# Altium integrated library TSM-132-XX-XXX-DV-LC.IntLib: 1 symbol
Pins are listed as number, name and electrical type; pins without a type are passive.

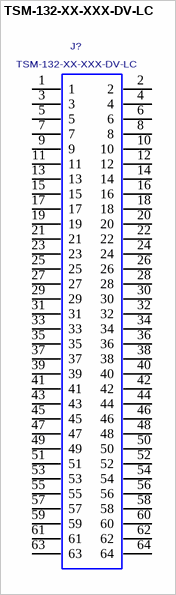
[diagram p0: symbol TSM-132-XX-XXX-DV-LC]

## TSM-132-XX-XXX-DV-LC
designator J?
Terminal Strip, Dual Row Vertical, Surface Mount, 0.100" Pitch, 64 Pins.; MANUFACTURER: SAMTEC
footprint TSM-132-XX-XXX-DV-LC
pins: 1, 2, 3, 4, 5, 6, 7, 8, 9, 10, 11, 12, 13, 14, 15, 16, 17, 18, 19, 20, 21, 22, 23, 24, 25, 26, 27, 28, 29, 30, 31, 32, 33, 34, 35, 36, 37, 38, 39, 40, 41, 42, 43, 44, 45, 46, 47, 48, 49, 50, 51, 52, 53, 54, 55, 56, 57, 58, 59, 60, 61, 62, 63, 64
